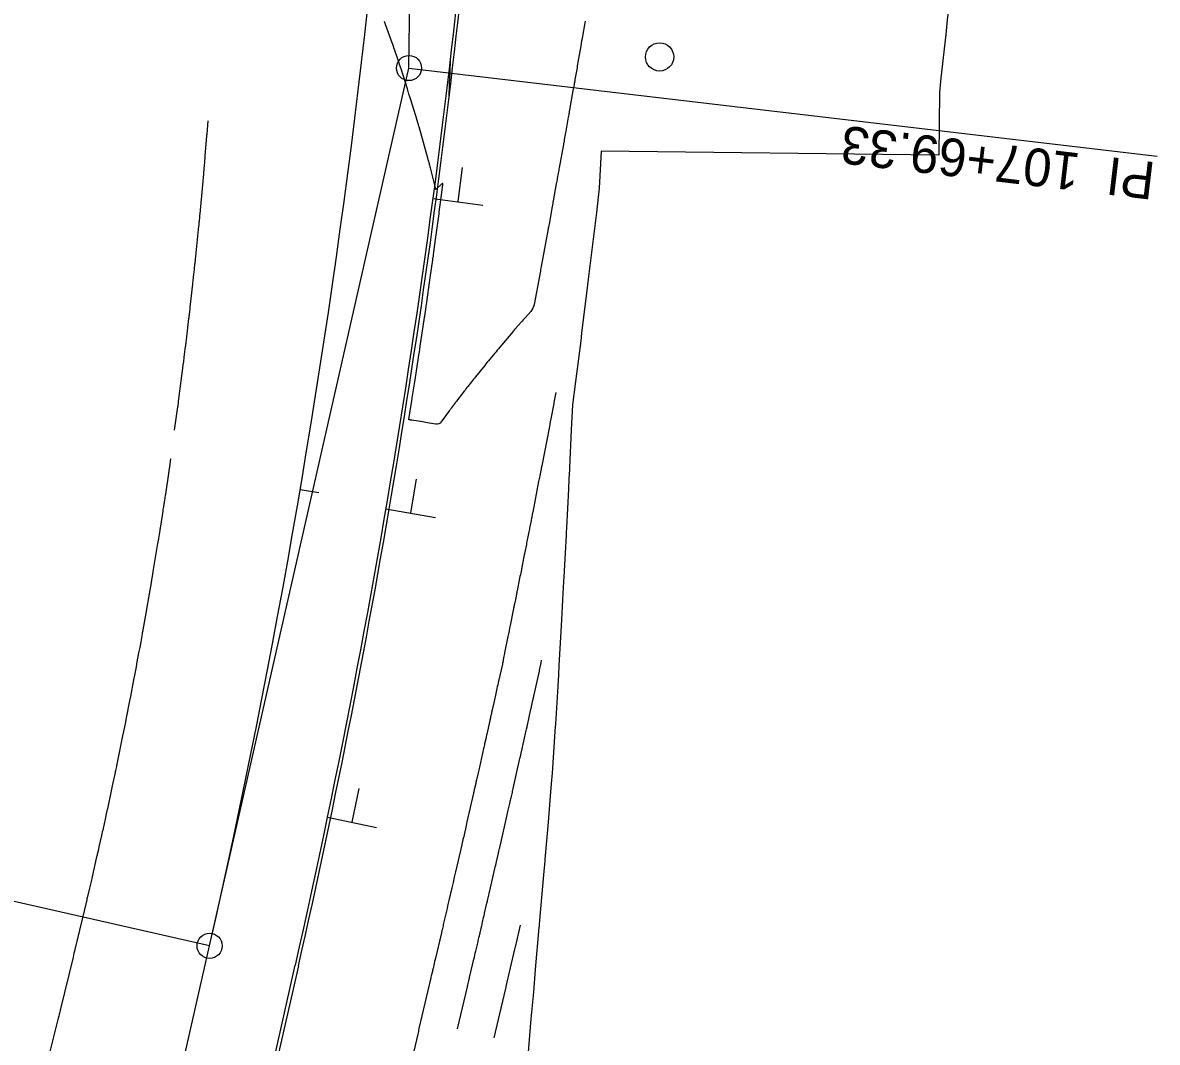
# Model space of a CAD drawing. Extents: x 1710723 to 1713003, y 548603 to 551142.
# Drawn here: x 1712421 to 1712601.7, y 550510.5 to 550672.9 of the extents above; entities that cross this region are included whole.
import ezdxf

# ---------------------------------------------------------------- set-up
doc = ezdxf.new("R2010")
doc.units = 0
for name, color, linetype in [('R_Contours', 7, 'Continuous'), ('R_Horz Alg', 7, 'Continuous'), ('R_Horz Alg Annot', 7, 'Continuous'), ('R_MOT', 7, 'Continuous'), ('R_No Plot', 7, 'Continuous'), ('R_Striping', 7, 'Continuous')]:
    doc.layers.add(name, color=color, linetype=linetype)

msp = doc.modelspace()

# ---------------------------------------------------------------- linework, layer by layer
at = {"layer": 'R_Contours'}
for points in [[(1712510.62, 550673.15), (1712510.57, 550672.87), (1712510.2, 550670.74), (1712510.13, 550670.36), (1712510.06, 550669.97), (1712510, 550669.59), (1712509.93, 550669.2), (1712509.47, 550666.58), (1712509.42, 550666.3), (1712509.37, 550666.01), (1712509.32, 550665.72), (1712509.27, 550665.43), (1712508.99, 550663.84), (1712508.98, 550663.78), (1712508.97, 550663.71), (1712508.96, 550663.65), (1712508.95, 550663.59), (1712508.88, 550663.21), (1712508.86, 550663.08), (1712508.79, 550662.69), (1712508.77, 550662.61), (1712508.76, 550662.52), (1712508.74, 550662.43), (1712508.73, 550662.35), (1712508.25, 550659.66), (1712508.17, 550659.2), (1712508.09, 550658.74), (1712508.01, 550658.28), (1712507.92, 550657.82), (1712507.48, 550655.3), (1712507.46, 550655.18), (1712507.44, 550655.07), (1712507.42, 550654.96), (1712507.4, 550654.85), (1712507.29, 550654.24), (1712507.25, 550654.03), (1712507.2, 550653.75), (1712507.19, 550653.68), (1712507.17, 550653.61), (1712507.16, 550653.54), (1712507.15, 550653.47), (1712506.48, 550649.74), (1712506.44, 550649.53), (1712506.4, 550649.32), (1712506.36, 550649.11), (1712506.33, 550648.9), (1712506.17, 550648.05), (1712506.14, 550647.84), (1712506.1, 550647.63), (1712506.06, 550647.42), (1712506.02, 550647.21), (1712505.53, 550644.52), (1712505.48, 550644.22), (1712505.39, 550643.71), (1712505.37, 550643.61), (1712505.35, 550643.51), (1712505.33, 550643.41), (1712505.31, 550643.31), (1712504.86, 550640.81), (1712504.81, 550640.57), (1712504.77, 550640.32), (1712504.76, 550640.26), (1712504.75, 550640.2), (1712504.73, 550640.14), (1712504.72, 550640.07), (1712503.61, 550634.02), (1712503.57, 550633.79), (1712503.52, 550633.55), (1712503.51, 550633.49), (1712503.5, 550633.43), (1712503.49, 550633.37), (1712503.48, 550633.31), (1712503.38, 550632.8), (1712503.38, 550632.76), (1712502.48, 550627.97), (1712502.41, 550627.67), (1712502.29, 550627.4), (1712502.14, 550627.14), (1712501.96, 550626.9), (1712501.04, 550625.89), (1712500.88, 550625.71), (1712500.72, 550625.53), (1712500.56, 550625.35), (1712500.4, 550625.17), (1712499.54, 550624.18), (1712499.5, 550624.13), (1712499.47, 550624.09), (1712499.43, 550624.04), (1712499.39, 550624), (1712499.23, 550623.82), (1712499.19, 550623.77), (1712499.15, 550623.73), (1712499.11, 550623.68), (1712499.08, 550623.64), (1712497.03, 550621.19), (1712496.83, 550620.95), (1712496.63, 550620.71), (1712496.43, 550620.47), (1712496.23, 550620.22), (1712495.42, 550619.26), (1712495.22, 550619.02), (1712495.02, 550618.78), (1712494.82, 550618.54), (1712494.62, 550618.29), (1712493.14, 550616.45), (1712492.99, 550616.26), (1712492.84, 550616.07), (1712492.69, 550615.88), (1712492.54, 550615.69), (1712491.94, 550614.94), (1712491.79, 550614.75), (1712491.64, 550614.56), (1712491.5, 550614.37), (1712491.35, 550614.18), (1712490.11, 550612.57), (1712490.06, 550612.51), (1712490.02, 550612.46), (1712489.98, 550612.4), (1712489.94, 550612.35), (1712489.77, 550612.13), (1712489.73, 550612.08), (1712489.69, 550612.02), (1712489.65, 550611.97), (1712489.61, 550611.91), (1712489.28, 550611.46), (1712489.21, 550611.36), (1712489.14, 550611.27), (1712489.07, 550611.17), (1712489, 550611.08), (1712487.69, 550609.28), (1712487.52, 550609.1), (1712487.33, 550608.98), (1712487.1, 550608.93), (1712486.85, 550608.94), (1712485.79, 550609.11), (1712485.53, 550609.16), (1712485.26, 550609.2), (1712485, 550609.24), (1712484.73, 550609.28), (1712482.99, 550609.56), (1712482.94, 550609.57), (1712482.89, 550609.58), (1712482.79, 550609.59), (1712482.74, 550609.6), (1712482.69, 550609.61), (1712482.58, 550609.63), (1712482.56, 550609.63), (1712482.54, 550609.65), (1712482.53, 550609.67), (1712482.53, 550609.69), (1712483.07, 550613.02), (1712483.08, 550613.08), (1712483.08, 550613.13), (1712483.48, 550615.67), (1712483.49, 550615.76), (1712483.51, 550615.84), (1712483.52, 550615.93), (1712483.53, 550616.01), (1712484.07, 550619.54), (1712484.14, 550619.99), (1712484.21, 550620.44), (1712484.28, 550620.89), (1712484.35, 550621.35), (1712484.97, 550625.55), (1712485, 550625.69), (1712485.02, 550625.84), (1712485.04, 550625.99), (1712485.06, 550626.13), (1712485.28, 550627.61), (1712485.29, 550627.71), (1712485.31, 550627.81), (1712485.32, 550627.91), (1712485.33, 550628.01), (1712485.94, 550632.22), (1712486.35, 550635.13), (1712486.36, 550635.19), (1712486.37, 550635.25), (1712486.44, 550635.74), (1712486.44, 550635.8), (1712486.45, 550635.85), (1712486.46, 550635.9), (1712486.47, 550635.95), (1712486.79, 550638.33), (1712487.35, 550642.46), (1712487.36, 550642.51), (1712487.37, 550642.57), (1712487.38, 550642.63), (1712487.39, 550642.69), (1712487.8, 550645.82), (1712487.81, 550645.87), (1712487.81, 550645.91), (1712487.96, 550647.07), (1712487.97, 550647.21), (1712487.94, 550647.27), (1712487.87, 550647.26), (1712487.76, 550647.18), (1712487.01, 550646.47), (1712486.95, 550646.41), (1712486.89, 550646.34), (1712486.87, 550646.33), (1712486.86, 550646.33), (1712486.85, 550646.34), (1712486.84, 550646.36), (1712485.97, 550649.77), (1712485.96, 550649.82), (1712485.94, 550649.87), (1712485.93, 550649.92), (1712485.92, 550649.98), (1712485.86, 550650.18), (1712485.85, 550650.24), (1712485.83, 550650.29), (1712485.82, 550650.34), (1712485.81, 550650.39), (1712485.66, 550650.91), (1712485.63, 550651.01), (1712485.6, 550651.12), (1712485.57, 550651.22), (1712485.54, 550651.32), (1712484.17, 550656.27), (1712484.13, 550656.4), (1712484.09, 550656.53), (1712484.06, 550656.66), (1712484.02, 550656.79), (1712483.83, 550657.45), (1712483.81, 550657.51), (1712483.79, 550657.57), (1712483.77, 550657.63), (1712483.75, 550657.69), (1712483.68, 550657.94), (1712483.66, 550658), (1712483.64, 550658.06), (1712483.63, 550658.12), (1712483.61, 550658.18), (1712482.83, 550660.62), (1712482.7, 550661.05), (1712482.56, 550661.48), (1712482.43, 550661.9), (1712482.3, 550662.33), (1712481.24, 550665.7), (1712481.22, 550665.76), (1712481.2, 550665.83), (1712481.18, 550665.89), (1712481.16, 550665.95), (1712481.07, 550666.21), (1712481.05, 550666.27), (1712481.03, 550666.34), (1712481.01, 550666.4), (1712480.99, 550666.46), (1712480.85, 550666.89), (1712480.82, 550666.98), (1712480.78, 550667.07), (1712480.75, 550667.16), (1712480.72, 550667.25), (1712480.25, 550668.62), (1712480.16, 550668.88), (1712480.07, 550669.14), (1712479.97, 550669.4), (1712479.88, 550669.66), (1712478.84, 550672.61), (1712478.67, 550673.1)], [(1712445.24, 550607.95), (1712445.75, 550611.67), (1712445.76, 550611.68), (1712445.77, 550611.79), (1712445.78, 550611.83), (1712445.85, 550612.4), (1712445.87, 550612.55), (1712446.67, 550618.71), (1712446.68, 550618.79), (1712446.69, 550618.86), (1712446.7, 550618.94), (1712446.71, 550619.01), (1712446.76, 550619.46), (1712446.78, 550619.61), (1712446.99, 550621.31), (1712447.01, 550621.44), (1712447.02, 550621.57), (1712447.04, 550621.69), (1712447.05, 550621.82), (1712447.13, 550622.46), (1712447.16, 550622.72), (1712447.17, 550622.85), (1712447.52, 550625.77), (1712447.54, 550625.92), (1712447.56, 550626.06), (1712447.57, 550626.21), (1712447.59, 550626.36), (1712447.66, 550626.95), (1712447.69, 550627.25), (1712447.72, 550627.55), (1712448.14, 550631.25), (1712448.15, 550631.3), (1712448.15, 550631.34), (1712448.16, 550631.39), (1712448.16, 550631.43), (1712448.2, 550631.75), (1712448.32, 550632.9), (1712448.34, 550633.08), (1712448.36, 550633.27), (1712448.38, 550633.46), (1712448.4, 550633.65), (1712448.48, 550634.4), (1712448.5, 550634.59), (1712448.52, 550634.78), (1712448.54, 550634.97), (1712448.56, 550635.16), (1712449.1, 550640.46), (1712449.1, 550640.5), (1712449.12, 550640.63), (1712449.15, 550641), (1712449.16, 550641.07), (1712449.16, 550641.13), (1712449.17, 550641.2), (1712449.18, 550641.27), (1712449.24, 550641.92), (1712449.26, 550642.19), (1712449.29, 550642.45), (1712449.77, 550647.62), (1712449.77, 550647.66), (1712449.78, 550647.71), (1712449.78, 550647.75), (1712449.78, 550647.8), (1712449.81, 550648.11), (1712449.82, 550648.15), (1712449.99, 550650.22), (1712450.03, 550650.58), (1712450.06, 550650.93), (1712450.09, 550651.29), (1712450.12, 550651.65), (1712450.38, 550654.81), (1712450.38, 550654.91), (1712450.39, 550654.95), (1712450.4, 550655.12), (1712450.56, 550657.26)], [(1712505.95, 550613.99), (1712505.65, 550612.4), (1712505.64, 550612.34), (1712505.62, 550612.22), (1712505.15, 550609.77), (1712505.13, 550609.67), (1712505.11, 550609.57), (1712505.09, 550609.47), (1712505.07, 550609.37), (1712504.97, 550608.88), (1712504.92, 550608.58), (1712503.7, 550602.28), (1712503.67, 550602.13), (1712503.67, 550602.11), (1712503.4, 550600.72), (1712503.35, 550600.48), (1712503.3, 550600.24), (1712503.26, 550600.01), (1712503.21, 550599.77), (1712502.27, 550594.92), (1712502.25, 550594.81), (1712502.22, 550594.7), (1712502.2, 550594.59), (1712502.18, 550594.47), (1712502.07, 550593.91), (1712502.02, 550593.68), (1712502, 550593.57), (1712501.81, 550592.59), (1712501.77, 550592.38), (1712501.73, 550592.18), (1712501.69, 550591.98), (1712501.65, 550591.78), (1712501.44, 550590.73), (1712501.39, 550590.49), (1712501.35, 550590.25), (1712501.3, 550590.01), (1712501.25, 550589.76), (1712500.87, 550587.85), (1712500.82, 550587.56), (1712500.76, 550587.27), (1712500.7, 550586.98), (1712500.64, 550586.69), (1712500.41, 550585.53), (1712500.35, 550585.24), (1712500.3, 550584.95), (1712500.24, 550584.66), (1712500.18, 550584.37), (1712499.79, 550582.39), (1712499.76, 550582.25), (1712499.73, 550582.1), (1712499.7, 550581.96), (1712499.67, 550581.82), (1712499.56, 550581.26), (1712499.51, 550580.98), (1712499.45, 550580.7), (1712499.33, 550580.13), (1712499.31, 550579.99), (1712499.28, 550579.84), (1712499.25, 550579.7), (1712499.22, 550579.56), (1712498.68, 550576.87), (1712498.59, 550576.42), (1712498.5, 550575.98), (1712498.41, 550575.54), (1712498.32, 550575.09), (1712497.79, 550572.48), (1712497.78, 550572.4), (1712497.73, 550572.16), (1712497.69, 550571.99), (1712497.58, 550571.41), (1712497.54, 550571.21), (1712497.48, 550570.95), (1712497.47, 550570.89), (1712497.46, 550570.83), (1712497.44, 550570.76), (1712497.43, 550570.7), (1712496.83, 550568), (1712496.77, 550567.7), (1712496.7, 550567.41), (1712496.63, 550567.11), (1712496.57, 550566.81), (1712496.28, 550565.5), (1712496.23, 550565.26), (1712496.17, 550565.02), (1712496.12, 550564.79), (1712496.07, 550564.55), (1712495.82, 550563.41), (1712495.78, 550563.27), (1712495.75, 550563.13), (1712495.72, 550562.99), (1712495.69, 550562.85), (1712495.56, 550562.28), (1712495.53, 550562.14), (1712495.5, 550562), (1712495.47, 550561.86), (1712495.44, 550561.72), (1712494.96, 550559.56), (1712494.91, 550559.37), (1712494.87, 550559.18), (1712494.83, 550558.98), (1712494.78, 550558.79), (1712494.61, 550558.02), (1712494.57, 550557.83), (1712494.52, 550557.64), (1712494.48, 550557.44), (1712494.44, 550557.25), (1712493.77, 550554.29), (1712493.72, 550554.06), (1712493.67, 550553.83), (1712493.62, 550553.6), (1712493.56, 550553.36), (1712493.32, 550552.28), (1712493.28, 550552.13), (1712493.25, 550551.98), (1712493.22, 550551.83), (1712493.18, 550551.68), (1712493.01, 550550.91), (1712492.96, 550550.71), (1712492.89, 550550.38), (1712492.88, 550550.32), (1712492.86, 550550.25), (1712492.85, 550550.19), (1712492.83, 550550.12), (1712491.79, 550545.55), (1712491.73, 550545.28), (1712491.67, 550545.01), (1712491.61, 550544.75), (1712491.55, 550544.48), (1712491.22, 550543.04), (1712491.2, 550542.96), (1712491.18, 550542.88), (1712491.16, 550542.79), (1712491.14, 550542.71), (1712491.03, 550542.21), (1712490.98, 550542), (1712490.96, 550541.9), (1712489.97, 550537.6), (1712489.92, 550537.39), (1712489.87, 550537.18), (1712489.82, 550536.97), (1712489.78, 550536.76), (1712489.58, 550535.92), (1712489.53, 550535.71), (1712489.49, 550535.5), (1712489.44, 550535.29), (1712489.39, 550535.08), (1712488.91, 550533.03), (1712488.86, 550532.82), (1712488.81, 550532.6), (1712488.72, 550532.18), (1712488.69, 550532.07), (1712488.67, 550531.96), (1712488.64, 550531.86), (1712488.62, 550531.75), (1712488.03, 550529.24), (1712487.98, 550529.02), (1712487.93, 550528.8), (1712487.83, 550528.35), (1712487.8, 550528.24), (1712487.78, 550528.13), (1712487.75, 550528.02), (1712487.72, 550527.91), (1712486.73, 550523.67), (1712486.65, 550523.33), (1712486.57, 550522.99), (1712486.39, 550522.2), (1712486.36, 550522.09), (1712486.33, 550521.97), (1712486.3, 550521.85), (1712486.28, 550521.73), (1712486.11, 550521.02), (1712486.06, 550520.83), (1712486.05, 550520.77), (1712486.04, 550520.71), (1712484.15, 550512.63), (1712484.1, 550512.41), (1712484.05, 550512.2), (1712484, 550511.98), (1712483.95, 550511.77), (1712481.92, 550502.91)], [(1712444.6, 550603.39), (1712444.42, 550602.17), (1712444.41, 550602.11), (1712444.4, 550602.05), (1712444.4, 550601.99), (1712444.39, 550601.93), (1712444.32, 550601.46), (1712443.76, 550597.75), (1712443.73, 550597.53), (1712443.69, 550597.3), (1712443.66, 550597.08), (1712443.63, 550596.86), (1712443.45, 550595.75), (1712443.38, 550595.31), (1712443.35, 550595.09), (1712442.97, 550592.67), (1712442.94, 550592.49), (1712442.92, 550592.32), (1712442.89, 550592.15), (1712442.86, 550591.97), (1712442.71, 550591.03), (1712442.66, 550590.73), (1712442.6, 550590.33), (1712442.58, 550590.24), (1712442.57, 550590.14), (1712442.55, 550590.04), (1712442.53, 550589.94), (1712441.79, 550585.45), (1712441.71, 550584.96), (1712441.62, 550584.46), (1712441.38, 550583.01), (1712441.37, 550582.97), (1712441.35, 550582.84), (1712441.32, 550582.64), (1712441.3, 550582.54), (1712441.24, 550582.16), (1712441.15, 550581.64), (1712441.13, 550581.54), (1712441.11, 550581.44), (1712441.09, 550581.34), (1712441.08, 550581.24), (1712440.82, 550579.78), (1712440.69, 550579.07), (1712440.18, 550576.14), (1712440.15, 550575.99), (1712440.12, 550575.83), (1712440.09, 550575.68), (1712440.06, 550575.52), (1712439.89, 550574.58), (1712439.84, 550574.27), (1712439.67, 550573.33), (1712439.63, 550573.12), (1712439.59, 550572.91), (1712439.55, 550572.7), (1712439.51, 550572.49), (1712439.24, 550571.05), (1712439.1, 550570.26), (1712438.9, 550569.22), (1712438.85, 550568.96), (1712438.8, 550568.7), (1712438.75, 550568.44), (1712438.7, 550568.18), (1712438.2, 550565.56), (1712438.06, 550564.86), (1712437.81, 550563.55), (1712437.78, 550563.39), (1712437.75, 550563.24), (1712437.72, 550563.08), (1712437.69, 550562.92), (1712437.48, 550561.88), (1712437.44, 550561.67), (1712437.43, 550561.62), (1712437.42, 550561.57), (1712437.41, 550561.52), (1712437.4, 550561.47), (1712437.09, 550559.95), (1712436.95, 550559.26), (1712435.98, 550554.52), (1712435.98, 550554.49), (1712435.97, 550554.46), (1712435.97, 550554.43), (1712435.96, 550554.41), (1712435.82, 550553.75), (1712435.81, 550553.67), (1712435.79, 550553.59), (1712435.77, 550553.51), (1712435.76, 550553.43), (1712435.3, 550551.3), (1712434.52, 550547.64), (1712434.49, 550547.5), (1712434.46, 550547.37), (1712434.43, 550547.23), (1712434.4, 550547.09), (1712434.17, 550546.01), (1712433.84, 550544.54), (1712433.78, 550544.25), (1712433.71, 550543.96), (1712433.65, 550543.67), (1712433.58, 550543.38), (1712433.19, 550541.62), (1712433.09, 550541.17), (1712432.96, 550540.58), (1712432.92, 550540.43), (1712432.89, 550540.28), (1712432.86, 550540.13), (1712432.82, 550539.98), (1712432.08, 550536.79), (1712431.92, 550536.06), (1712431.57, 550534.57), (1712431.55, 550534.47), (1712431.52, 550534.36), (1712431.5, 550534.26), (1712431.47, 550534.15), (1712431.31, 550533.45), (1712431.27, 550533.29), (1712431.26, 550533.25), (1712431.25, 550533.21), (1712431.24, 550533.17), (1712431.23, 550533.13), (1712429.36, 550525.26), (1712429.28, 550524.96), (1712429.21, 550524.65), (1712429.14, 550524.35), (1712429.06, 550524.04), (1712427, 550515.55), (1712426.93, 550515.24), (1712426.85, 550514.93), (1712426.77, 550514.62), (1712426.7, 550514.31), (1712424.59, 550505.81)], [(1712490.3, 550512.59), (1712491.86, 550519.27), (1712491.88, 550519.35), (1712491.9, 550519.44), (1712491.92, 550519.52), (1712491.94, 550519.61), (1712492.05, 550520.05), (1712492.09, 550520.25), (1712492.15, 550520.51), (1712492.17, 550520.58), (1712492.18, 550520.64), (1712492.2, 550520.71), (1712492.22, 550520.77), (1712492.9, 550523.71), (1712492.98, 550524.02), (1712493.05, 550524.33), (1712493.12, 550524.65), (1712493.19, 550524.96), (1712493.5, 550526.24), (1712493.56, 550526.54), (1712493.63, 550526.84), (1712493.7, 550527.13), (1712493.77, 550527.43), (1712494.1, 550528.85), (1712494.15, 550529.03), (1712494.19, 550529.22), (1712494.23, 550529.4), (1712494.27, 550529.58), (1712494.44, 550530.32), (1712494.49, 550530.5), (1712494.53, 550530.68), (1712494.57, 550530.87), (1712494.61, 550531.05), (1712494.98, 550532.64), (1712495.02, 550532.8), (1712495.06, 550532.96), (1712495.09, 550533.12), (1712495.13, 550533.28), (1712495.28, 550533.92), (1712495.31, 550534.08), (1712495.35, 550534.24), (1712495.39, 550534.4), (1712495.43, 550534.56), (1712496.25, 550538.16), (1712496.31, 550538.41), (1712496.37, 550538.67), (1712496.43, 550538.93), (1712496.49, 550539.19), (1712496.81, 550540.57), (1712496.83, 550540.65), (1712496.84, 550540.73), (1712496.86, 550540.81), (1712496.88, 550540.89), (1712496.98, 550541.33), (1712497.01, 550541.43), (1712497.05, 550541.61), (1712497.06, 550541.68), (1712497.07, 550541.71), (1712498.21, 550546.71), (1712498.26, 550546.94), (1712498.31, 550547.18), (1712498.37, 550547.41), (1712498.42, 550547.65), (1712498.66, 550548.72), (1712498.7, 550548.89), (1712498.74, 550549.05), (1712498.78, 550549.22), (1712498.81, 550549.38), (1712499.02, 550550.27), (1712499.06, 550550.48), (1712499.11, 550550.68), (1712499.13, 550550.78), (1712499.15, 550550.89), (1712500.12, 550555.17), (1712500.18, 550555.43), (1712500.24, 550555.69), (1712500.35, 550556.21), (1712500.38, 550556.34), (1712500.41, 550556.47), (1712500.44, 550556.6), (1712500.47, 550556.73), (1712501.23, 550560.11), (1712501.28, 550560.33), (1712501.36, 550560.7), (1712501.37, 550560.78), (1712501.39, 550560.85), (1712501.41, 550560.92), (1712501.42, 550561), (1712501.98, 550563.52), (1712502.02, 550563.66), (1712502.05, 550563.81), (1712502.07, 550563.89), (1712502.08, 550563.96), (1712503.32, 550569.56), (1712503.35, 550569.68), (1712503.35, 550569.7), (1712503.35, 550569.72), (1712503.36, 550569.73), (1712503.36, 550569.75), (1712503.6, 550570.93), (1712503.68, 550571.31)], [(1712496.13, 550511.16), (1712497.71, 550517.91), (1712497.73, 550518.01), (1712497.75, 550518.11), (1712497.78, 550518.21), (1712497.8, 550518.31), (1712498.02, 550519.23), (1712498.04, 550519.33), (1712498.04, 550519.35), (1712499.44, 550525.29), (1712499.49, 550525.51), (1712499.5, 550525.59), (1712500.33, 550529.12)]]:
    msp.add_lwpolyline(points, dxfattribs=at)
at = {"layer": 'R_Horz Alg'}
msp.add_line((1712246.77, 549627.28), (1712450.81, 550525.82), dxfattribs=at)
msp.add_arc((1711136.14, 550824.35), 1348.14, 347.20664, 359.34976, dxfattribs=at)
at = {"layer": 'R_Horz Alg Annot'}
for p, q in [((1712482.56, 550665.66), (1712484.19, 550809.05)), ((1712450.81, 550525.82), (1712482.56, 550665.66))]:
    msp.add_line(p, q, dxfattribs=at)
for points in [[(1712482.56, 550665.66), (1712601.74, 550651.62)], [(1712468.18, 550597.97), (1712465.22, 550598.47)], [(1712450.81, 550525.82), (1712333.79, 550552.4)]]:
    msp.add_lwpolyline(points, dxfattribs=at)
for centre in [(1712482.56, 550665.66), (1712450.81, 550525.82)]:
    msp.add_circle(centre, 2, dxfattribs=at)
at = {"layer": 'R_MOT'}
for p, q in [((1712567.07, 550661.79), (1712566.95, 550651.79)), ((1712566.95, 550651.79), (1712513.19, 550652.43)), ((1712490.38, 550644.39), (1712491.1, 550649.8)), ((1712494.31, 550643.75), (1712486.38, 550644.8)), ((1712482.86, 550594.81), (1712483.78, 550600.19)), ((1712486.77, 550594.02), (1712478.88, 550595.37)), ((1712473.53, 550545.54), (1712474.65, 550550.89)), ((1712477.41, 550544.61), (1712469.57, 550546.25)), ((1712436.58, 550399.92), (1712464.46, 550522.72))]:
    msp.add_line(p, q, dxfattribs=at)
msp.add_lwpolyline([(1712513.19, 550652.43), (1712512.83, 550646.5), (1712512.44, 550642.66), (1712511.96, 550638.81), (1712511.16, 550632.44), (1712510.99, 550631.13), (1712510.05, 550623.44), (1712509.92, 550622.21), (1712509.07, 550615.75), (1712508.62, 550611.99), (1712508.41, 550608.02), (1712508.12, 550601.97), (1712508.1, 550601.64), (1712508.03, 550600.23), (1712507.94, 550598.58), (1712507.63, 550592.43), (1712507.63, 550592.3), (1712507.6, 550591.8), (1712507.57, 550591.27), (1712507.57, 550591.27), (1712507.47, 550589.32), (1712507.23, 550584.63), (1712507.19, 550583.88), (1712507.03, 550581.02), (1712507.03, 550580.89), (1712506.81, 550576.82), (1712506.45, 550570.49), (1712506.36, 550569), (1712506.2, 550566.26), (1712505.87, 550561.18), (1712505.8, 550560.09), (1712505.79, 550559.97), (1712505.34, 550553.35), (1712505.22, 550551.64), (1712505.06, 550549.69), (1712504.7, 550545.54), (1712504.2, 550539.56), (1712504.18, 550539.29), (1712504.04, 550537.72), (1712503.36, 550529.93), (1712503.36, 550529.89), (1712503.3, 550529.19), (1712503.27, 550528.88), (1712503.26, 550528.76), (1712502.68, 550522.05), (1712502.37, 550518.45), (1712501.99, 550514.2), (1712501.47, 550508.24)], dxfattribs=at)
msp.add_circle((1712522.48, 550667.43), 2.25, dxfattribs=at)
for centre, radius, start, end in [((1711136.14, 550824.35), 1440.14, 353.51869, 359.42679), ((1711136.14, 550824.35), 1362.14, 347.20664, 355.33721), ((1710070.75, 550756.96), 2420.1, 357.725, 357.87398)]:
    msp.add_arc(centre, radius, start, end, dxfattribs=at)
at = {"layer": 'R_No Plot'}
msp.add_line((1712464.95, 550522.61), (1712459.21, 550497.33), dxfattribs=at)
msp.add_arc((1711136.14, 550824.35), 1362.64, 347.20664, 354.06382, dxfattribs=at)
at = {"layer": 'R_Striping'}
msp.add_line((1712369.36, 550167.14), (1712450.81, 550525.82), dxfattribs=at)
msp.add_arc((1711136.14, 550824.35), 1348.14, 347.20664, 359.34976, dxfattribs=at)

# ---------------------------------------------------------------- texts
at = {"layer": 'R_Horz Alg Annot'}
msp.add_text('PI  107+69.33', height=6, rotation=173.2782, dxfattribs=at).set_placement((1712601.62, 550650.62))

doc.saveas('drawing.dxf')
